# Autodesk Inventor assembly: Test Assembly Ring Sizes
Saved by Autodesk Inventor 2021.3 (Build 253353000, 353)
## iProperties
Created: 2022-02
Part Number: Test Assembly Ring Sizes
Document SubType Name: Assembly
Designer: Administrator
Title: Test Assembly Ring Sizes v6
Author: Administrator
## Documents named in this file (4)
- c:\worker\convert-fusion-r01\tmp\job-1\417\output\files\da1dd972-262c-43a0-bcdf-9db6a1cc4b0e\84aff9bc-f083-4002-8cc7-0b12fa34ab43.iam
- c:\worker\convert-fusion-r01\tmp\job-1\417\output\files\da1dd972-262c-43a0-bcdf-9db6a1cc4b0e\ring 2.ipt
- c:\worker\convert-fusion-r01\tmp\job-1\417\output\files\da1dd972-262c-43a0-bcdf-9db6a1cc4b0e\ring 3.ipt
- c:\worker\convert-fusion-r01\tmp\job-1\417\output\files\da1dd972-262c-43a0-bcdf-9db6a1cc4b0e\ring 1.ipt
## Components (3 placed, 3 different names)
1. ring 2:1
2. ring 3:1
3. ring 1:1
